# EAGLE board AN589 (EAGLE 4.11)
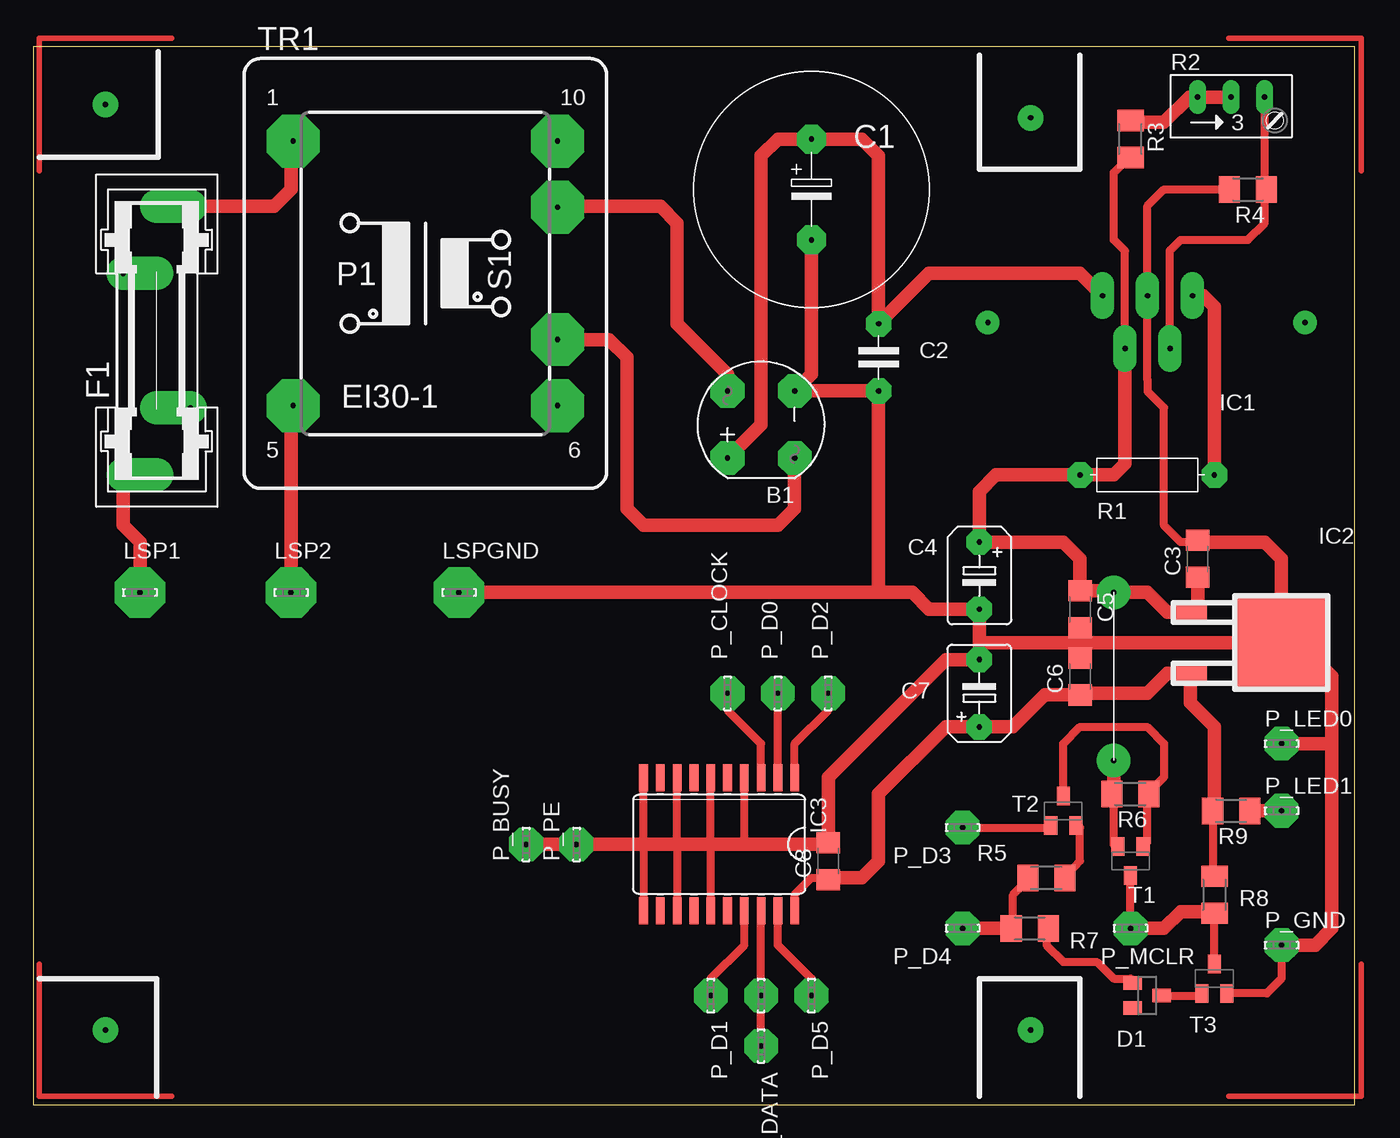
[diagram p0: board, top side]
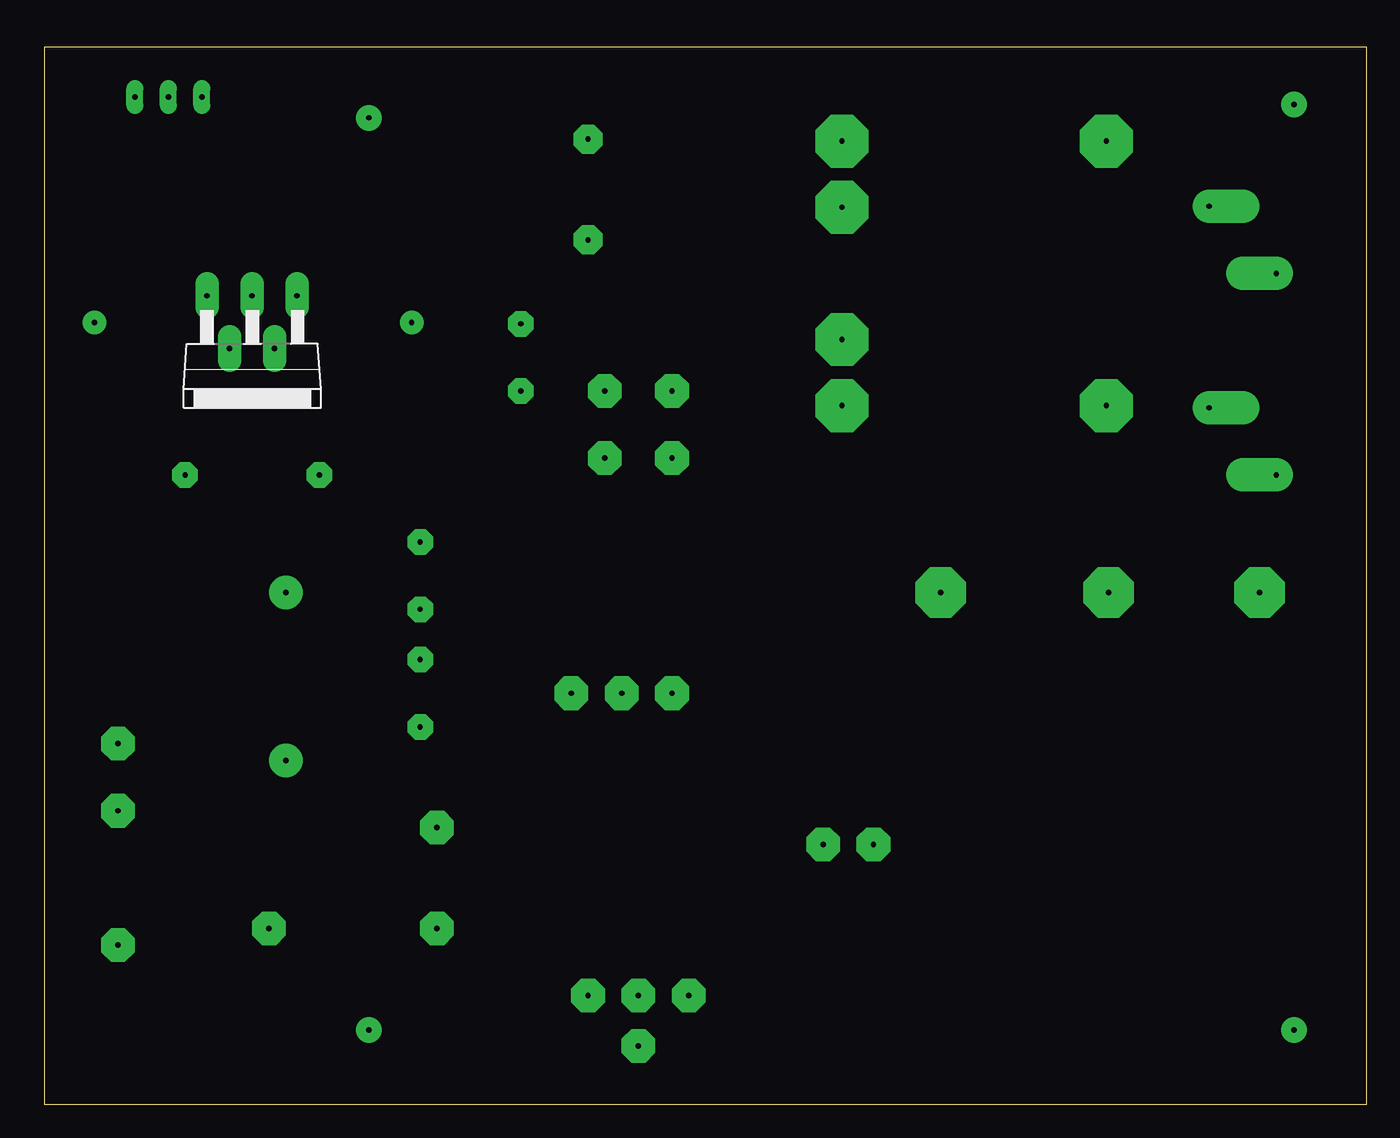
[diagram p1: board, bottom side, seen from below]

Size 100 x 80 mm. Coordinates in mm from the lower left corner, seen from the top.
Outline: 0,0 100,0 100,80 0,80 0,0
Copper layers (1*16): Top 0.035mm / dielectric 1.5mm / Bottom 0.035mm
Design rules "default": minimum track width 10mil, minimum drill 24mil, track to track 8mil, track to pad 8mil, pad to pad 8mil, via to via 8mil, smd to smd 8mil, copper to edge 40mil, drill to drill 8mil, minimum pad ring 10mil, minimum via ring 8mil, stop-mask expansion 4mil, vias tented up to drill 0mil, thermal gap 10mil

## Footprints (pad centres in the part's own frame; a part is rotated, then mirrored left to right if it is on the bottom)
RB1A = drill 0.406 pad 2.54 octagon: P$1 2.54,-2.54; P$2 2.54,2.54; P$3 -2.54,2.54; P$4 -2.54,-2.54
ES-7,5 = drill 0.406 pad 2.184 octagon: 1 -3.81,0; 2 3.81,0
C-5 = drill 0.406 pad 1.93 octagon: 1 -2.54,0; 2 2.54,0
C1206 = smd 1.6 x 1.8: 1 -1.4,0; 2 1.4,0
B45181B = drill 0.406 pad 1.93 octagon: + -2.54,0; - 2.54,0
SOT23 = smd 1 x 1.4: 1 -0.95,-1.1; 2 0.95,-1.1; 3 0,1.1
GSH15A = drill 0.406 pad 2.54 offset: 1 -10.16,2.54; 2 10.16,-2.54; P$3 -5.08,-2.54; P$4 5.08,2.54
L200S = drill 0.406 pad 1.778 long: 1 -3.378,-8.472; 2 -1.678,-4.472; 3 0.022,-8.472; 4 1.722,-4.472; 5 3.422,-8.472
D-PAK(TO-252) = smd 1.5 x 2.5: P$1 -2.3,-6.9; P$3 2.3,-6.9 | smd 7 x 7: P$2 0,0
SO20W = smd 0.66 x 2.032: 1 -5.715,-5.029; 2 -4.445,-5.029; 3 -3.175,-5.029; 4 -1.905,-5.029; 5 -0.635,-5.029; 6 0.635,-5.029; 7 1.905,-5.029; 8 3.175,-5.029; 9 4.445,-5.029; 10 5.715,-5.029; 11 5.715,5.029; 12 4.445,5.029; 13 3.175,5.029; 14 1.905,5.029; 15 0.635,5.029; 16 -0.635,5.029; 17 -1.905,5.029; 18 -3.175,5.029; 19 -4.445,5.029; 20 -5.715,5.029
LSP20 = drill 0.406 pad 3.81 octagon: 1 0,0
LSP10 = drill 0.406 pad 2.54 octagon: P$3 0,0
R-10 = drill 0.406 pad 1.93 octagon: P$1 -5.08,0; P$2 5.08,0
RJ9W = drill 0.406 pad 1.27 long: A 2.54,0.635; E -2.54,0.635; S 0,0.635
M1206 = smd 1.6 x 2: 1 -1.4,0; 2 1.4,0
SOT23-BEC = smd 1 x 1.4: B -0.95,-1.1; C 0,1.1; E 0.95,-1.1
EI30-1 = drill 0.406 pad 4 octagon: 1 -10,10; 5 -10,-10; 6 10,-10; 7 10,-5; 9 10,5; 10 10,10
STRAP_500 = drill 0.406 pad 2.54 round: 1 -6.35,0; 2 6.35,0

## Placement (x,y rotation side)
B1  [RB1A]  55.08,51.43 90 top
C1  680 µF  [ES-7,5]  58.89,69.21 270 top
C2  100 nF  [C-5]  63.97,56.51 270 top
C3  100 nF  [C1206]  88.1,41.27 90 top
C4  10 µF  [B45181B]  71.59,40 270 top
C5  100 nF  [C1206]  79.21,37.46 270 top
C6  100 nF  [C1206]  79.21,32.38 90 top
C7  10 µF  [B45181B]  71.59,31.11 90 top
C8  100 nF  [C1206]  60.16,18.41 90 top
D1  [SOT23]  84.29,8.25 270 top
F1  [GSH15A]  9.36,57.78 90 top
IC1  L200  [L200S]  84.29,52.7 180 bottom
IC2  78M05CDT  [D-PAK(TO-252)]  94.45,34.92 270 top
IC3  74LS244DW  [SO20W]  51.91,19.68 180 top
LSP1  LSP20  [LSP20]  8.09,38.73 0 top
LSP2  LSP20  [LSP20]  19.52,38.73 0 top
LSPGND  LSP20  [LSP20]  32.22,38.73 0 top
P_ACK  LSP10  [LSP10]  55.08,8.25 90 top
P_BUSY  LSP10  [LSP10]  37.3,19.68 90 top
P_CLOCK  LSP10  [LSP10]  52.54,31.11 90 top
P_D0  LSP10  [LSP10]  56.35,31.11 90 top
P_D1  LSP10  [LSP10]  51.27,8.25 90 top
P_D2  LSP10  [LSP10]  60.16,31.11 90 top
P_D3  LSP10  [LSP10]  70.32,20.95 0 top
P_D4  LSP10  [LSP10]  70.32,13.33 0 top
P_D5  LSP10  [LSP10]  58.89,8.25 90 top
P_DATA  LSP10  [LSP10]  55.08,4.44 90 top
P_GND  LSP10  [LSP10]  94.45,12.06 0 top
P_LED0  LSP10  [LSP10]  94.45,27.3 0 top
P_LED1  LSP10  [LSP10]  94.45,22.22 0 top
P_MCLR  LSP10  [LSP10]  83.02,13.33 0 top
P_PE  LSP10  [LSP10]  41.11,19.68 90 top
R1  4.7  [R-10]  84.29,47.62 0 top
R2  2.2k  [RJ9W]  90.64,75.56 0 top
R3  1.8k  [M1206]  83.02,73.02 270 top
R4  820  [M1206]  91.91,69.21 180 top
R5  1.8k  [M1206]  76.67,17.14 0 top
R6  1.8k  [M1206]  83.02,23.49 180 top
R7  1.8k  [M1206]  75.4,13.33 180 top
R8  1.8k  [M1206]  89.37,15.87 90 top
R9  270  [M1206]  90.64,22.22 180 top
T1  PMBT2907  [SOT23-BEC]  83.02,18.41 180 top
T2  PMBT2222  [SOT23-BEC]  77.94,22.22 0 top
T3  PMBT2222  [SOT23-BEC]  89.37,9.52 0 top
TR1  [EI30-1]  29.68,62.86 0 top
U$1  [STRAP_500]  81.75,32.38 90 top

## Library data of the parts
B1 = rectifier
C1 C2 R1 = discrete
C3 C5 C6 C8 = capacitor-smd
C4 C7 R3-R9 = rcl
D1 = semicon-smd-ipc
F1 = fuse
IC1 IC2 = v-reg
IC3 = 74xx-us
LSP1 LSP2 LSPGND P_ACK P_BUSY P_CLOCK P_D0 P_D1-P_D5 P_DATA P_GND P_LED0 P_LED1 P_MCLR P_PE = solpad
R2 = pot
T1-T3 = transistor-pnp
TR1 = trafo
U$1 = straps

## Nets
GND: B1.P$1 C1.2 C2.2 C3.2 C4.- C5.2 C6.2 C7.- C8.2 IC1.3 IC2.P$2 IC3.4 IC3.6 IC3.8 IC3.10 IC3.11 IC3.13 IC3.15 LSPGND.1 P_BUSY.P$3 P_GND.P$3 P_LED0.P$3 P_PE.P$3 R4.2 T3.E
N$1: IC1.5 R1.P$2
N$2: R6.1 T1.B T2.C
N$3: R5.2 T2.E
N$4: P_MCLR.P$3 R8.1 T1.C T3.C
N$5: F1.1 LSP1.1
N$6: F1.2 TR1.1
N$7: LSP2.1 TR1.5
N$8: B1.P$2 TR1.9
N$9: B1.P$4 TR1.7
N$10: IC3.1 P_D2.P$3
N$11: B1.P$3 C1.1 C2.1 IC1.1
N$12: D1.1 R7.1
N$13: D1.3 T3.B
N$14: C3.1 C4.+ C5.1 IC1.2 IC2.P$1 R1.P$1 R3.2 U$1.2
N$15: R2.E R2.S R3.1
N$16: IC1.4 R2.A R4.1
N$17: P_D3.P$3 T2.B
N$18: P_D4.P$3 R5.1 R7.2
N$19: P_LED1.P$3 R9.1
N$20: R6.2 T1.E U$1.1
N$21: IC3.2 P_D0.P$3
N$23: IC3.18 P_ACK.P$3 P_DATA.P$3
N$24: IC3.17 P_D1.P$3
N$25: IC3.19 P_D5.P$3
N$26: IC3.3 P_CLOCK.P$3
VCC: C6.1 C7.+ C8.1 IC2.P$3 IC3.20 R8.2 R9.2

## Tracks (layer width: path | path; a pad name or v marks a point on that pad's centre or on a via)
GND
  Top 0.61: 60.16,19.68 C8.2 | P_GND.P$3 94.45,9.52 93.35,8.42 T3.E | 46.19,14.6 IC3.11 46.19,19.68 IC3.10 | IC3.13 48.73,19.68 IC3.8 | IC3.15 51.27,19.68 IC3.6 | 53.81,19.68 IC3.4 | 90.64,69.21 R4.2 85.56,69.21 84.31,67.96 IC1.3 84.31,54.79 84.34,54.77 84.34,53.92 85.56,52.7 85.56,43.81 86.83,42.54 88.1,42.54
  Top 1.016: 71.59,34.92 C4.- 67.78,37.46 66.51,38.73 63.97,38.73 | 79.21,33.65 C6.2 79.21,34.92 | 79.21,34.92 C5.2 | 79.21,34.92 79.21,36.19 | 71.59,34.92 79.21,34.92 | 79.21,34.92 IC2.P$2 | IC2.P$2 95.72,34.92 98.26,32.38 98.26,27.3 | 98.26,27.3 P_LED0.P$3 | 98.26,27.3 98.26,13.33 96.99,12.06 P_GND.P$3 | P_BUSY.P$3 P_PE.P$3 46.19,19.68 48.73,19.68 51.27,19.68 53.81,19.68 60.16,19.68 | 71.59,34.92 C7.- 69.05,33.65 60.16,24.76 C8.2 | C1.2 58.89,55.24 B1.P$1 C2.2 63.97,38.73 | 63.97,38.73 LSPGND.1 | IC2.P$2 94.45,41.27 93.18,42.54 88.1,42.54 C3.2
N$1
  Top 1.016: IC1.5 88.52,61.17 89.37,60.32 R1.P$2
N$2
  Top 0.61: 84.29,23.49 R6.1 | T2.C 77.94,27.3 79.21,28.57 84.29,28.57 85.56,27.3 85.56,24.76 84.29,23.49 | T1.B 84.29,19.83 84.29,23.49
N$3
  Top 0.61: R5.2 79.21,18.41 79.21,20.95 T2.E
N$4
  Top 0.61: T3.C R8.1 | P_MCLR.P$3 T1.C
  Top 1.016: R8.1 89.24,14.6 86.83,14.6 85.56,13.33 P_MCLR.P$3
N$5
  Top 1.016: F1.1 6.82,43.81 8.09,42.54 LSP1.1
N$6
  Top 1.016: F1.2 18.25,67.94 19.52,69.21 19.52,73.02 TR1.1
N$7
  Top 1.016: TR1.5 19.52,52.7 LSP2.1
N$8
  Top 1.016: B1.P$2 52.54,55.24 48.73,59.05 48.73,66.67 47.46,67.94 39.84,67.94 39.76,67.86 TR1.9
N$9
  Top 1.016: TR1.7 43.57,57.86 44.92,56.51 44.92,45.08 46.19,43.81 56.35,43.81 57.62,45.08 B1.P$4
N$10
  Top 0.61: P_D2.P$3 60.16,29.84 57.62,27.3 IC3.1
N$11
  Top 1.016: B1.P$3 55.08,51.43 55.08,71.75 56.35,73.02 C1.1 62.7,73.02 63.97,71.75 C2.1 67.78,62.86 79.21,62.86 80.9,61.17 IC1.1
N$12
  Top 0.254: D1.1 83.02,9.52 | R7.1 76.67,13.33
  Top 0.61: 76.67,13.33 76.67,12.06 77.94,10.79 80.48,10.79 81.75,9.52 83.02,9.52
N$13
  Top 0.61: T3.B 88.27,8.42 88.1,8.25 D1.3
N$14
  Top 0.61: IC1.2 82.61,64.57 82.59,64.59 82.59,64.56 | 82.59,64.53 82.59,64.56 | 82.59,64.56 81.75,65.4 81.75,70.48 83.02,71.75 R3.2
  Top 1.016: C3.1 88.1,37.46 87.86,37.22 IC2.P$1 85.8,37.22 84.29,38.73 U$1.2 81.62,38.86 C5.1 | C5.1 79.21,38.73 | C5.1 79.21,41.27 77.94,42.54 C4.+ 71.59,46.35 72.86,47.62 R1.P$1 81.75,47.62 82.61,48.48 IC1.2
N$15
  Top 1.016: R3.1 83.02,74.29 85.56,74.29 87.47,76.19 R2.E R2.S
N$16
  Top 0.61: R4.1 93.18,69.21 | 93.18,69.21 R2.A | IC1.4 86.01,64.63 86.02,64.64 86.07,64.64 86.83,65.4 91.91,65.4 93.18,66.67 93.18,69.21
N$17
  Top 0.61: T2.B 76.67,20.95 P_D3.P$3
N$18
  Top 0.61: R7.2 74.13,13.33 74.13,15.87 75.27,17.01 R5.1
  Top 1.016: P_D4.P$3 74.13,13.33
N$19
  Top 0.254: R9.1 91.91,22.22
  Top 1.016: 91.91,22.22 P_LED1.P$3
N$20
  Top 0.61: R6.2 81.75,23.49 81.75,19.68 T1.E
  Top 1.016: U$1.1 81.75,23.49
N$21
  Top 0.61: IC3.2 P_D0.P$3
N$22
  Top 0.406: 0.47,70.63 0.47,80.63 10.47,80.63
N$23
  Top 0.61: P_DATA.P$3 P_ACK.P$3 IC3.18
N$24
  Top 0.61: IC3.17 53.81,12.06 51.27,9.52 P_D1.P$3
N$25
  Top 0.61: IC3.19 56.35,12.06 58.89,9.52 P_D5.P$3
N$26
  Top 0.61: P_CLOCK.P$3 52.54,29.84 55.08,27.3 IC3.3
N$27
  Top 0.406: 0.47,10.63 0.47,0.63 10.47,0.63
N$28
  Top 0.406: 100.47,10.63 100.47,0.63 90.47,0.63
N$29
  Top 0.406: 90.47,80.63 100.47,80.63 100.47,70.63
N$32  (via drill 0.41 pad 1.78)
  other vias: 72.23,59.16
N$34  (via drill 0.41 pad 1.78)
  other vias: 96.23,59.16
S$2  (via drill 0.41 pad 1.93)
  other vias: 5.47,5.63
S$3  (via drill 0.41 pad 1.93)
  other vias: 75.47,5.63
S$4  (via drill 0.41 pad 1.93)
  other vias: 75.47,74.63
S$5  (via drill 0.41 pad 1.93)
  other vias: 5.47,75.63
VCC
  Top 0.254: 89.37,17.14 R8.2
  Top 0.61: C8.1 60.16,17.14 58.89,17.14 57.62,15.87 IC3.20 | R9.2 89.24,17.27 89.37,17.14
  Top 1.016: R9.2 89.37,22.22 89.37,28.57 87.55,30.39 IC2.P$3 85.8,32.62 84.29,31.11 79.21,31.11 C6.1 76.54,30.98 74.13,28.57 C7.+ 69.05,28.57 63.97,23.49 63.97,18.41 62.7,17.14 60.16,17.14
